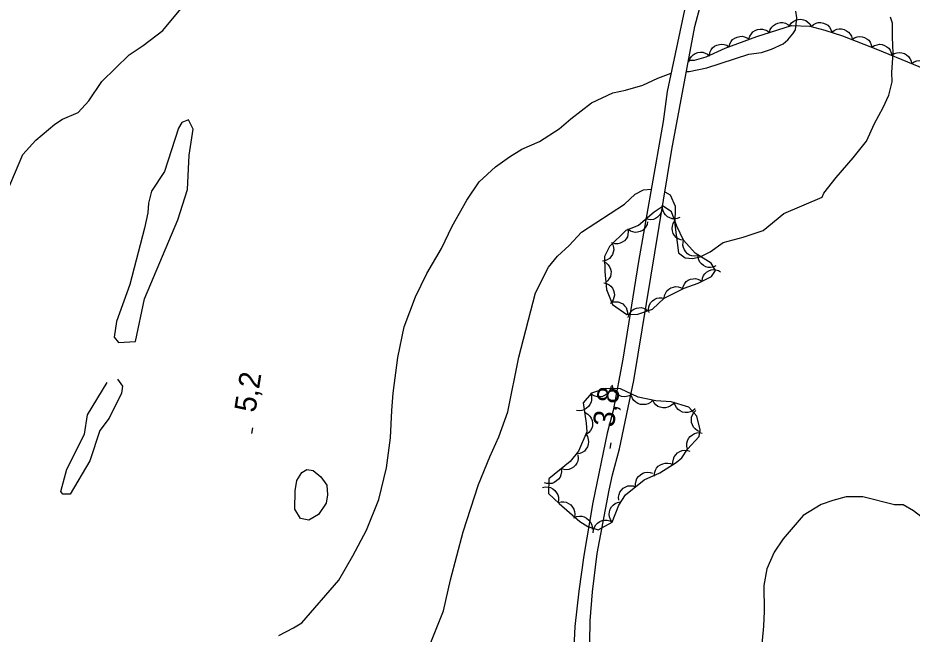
# Model space of a CAD drawing. Extents: x 282461 to 284471, y 5554090 to 5557646.
# Drawn here: x 283624.2 to 283749.2, y 5554829.7 to 5554915.9 of the extents above; entities that cross this region are included whole.
import ezdxf

# ---------------------------------------------------------------- set-up
doc = ezdxf.new("R2010")
doc.units = 0
for name, color, linetype in [('Niveau 1', 7, 'Continuous'), ('Niveau 19', 7, 'Continuous'), ('Niveau 2', 7, 'Continuous'), ('Niveau 3', 7, 'Continuous'), ('Niveau 44', 7, 'Continuous')]:
    doc.layers.add(name, color=color, linetype=linetype)

msp = doc.modelspace()

# ---------------------------------------------------------------- linework, layer by layer
at = {"layer": 'Niveau 1'}
for points in [[(283634.13, 5554904.29), (283635.96, 5554906.98), (283639.76, 5554910.72), (283641.72, 5554912.02), (283644.49, 5554914.13), (283647.01, 5554917.17)], [(283717.72, 5554908.41), (283718.09, 5554908.41), (283720.53, 5554908.89), (283726.44, 5554910.8), (283728.19, 5554911.05), (283729.58, 5554911.53), (283731.2, 5554912.24), (283731.89, 5554912.82), (283732.58, 5554913.64), (283732.92, 5554914.22), (283733.11, 5554915.88), (283732.98, 5554916.81)], [(283660.69, 5554829.5), (283662.78, 5554830.56), (283663.93, 5554831.27), (283669.1, 5554837.23), (283671.04, 5554840.61), (283672.97, 5554844.22), (283674.67, 5554848.52), (283675.78, 5554852.94), (283676.32, 5554857.12), (283676.5, 5554860.95), (283676.71, 5554863.38), (283677.35, 5554868.38), (283678.23, 5554872.68), (283679.81, 5554876.87), (283681.4, 5554880.13), (283683.46, 5554883.62), (283684.94, 5554886.77), (283686.99, 5554890.38), (283688.71, 5554892.95), (283691.01, 5554895.06), (283692.97, 5554896.47), (283694.7, 5554897.53), (283697.14, 5554898.59), (283699.91, 5554900.36), (283701.52, 5554901.76), (283704.41, 5554903.99), (283707.41, 5554905.41), (283709.16, 5554905.77), (283711.59, 5554906.49), (283713.68, 5554907.44), (283715.18, 5554908.03), (283715.58, 5554908.16)], [(283622.09, 5554890.04), (283624.92, 5554896.79), (283626.75, 5554898.78), (283629.4, 5554901.01), (283630.44, 5554901.71), (283632.64, 5554902.66), (283634.13, 5554904.29)]]:
    msp.add_lwpolyline(points, dxfattribs=at)
at = {"layer": 'Niveau 19'}
for points in [[(283720.93, 5554937.34), (283721.46, 5554934.2), (283721.54, 5554932.22), (283721.37, 5554930.64), (283720.93, 5554929.07), (283720.02, 5554926.98), (283718.22, 5554920.81), (283715, 5554905.6), (283714.45, 5554901.38), (283710.98, 5554881.79), (283708.81, 5554868.14), (283707.44, 5554860.94), (283706.6, 5554857.8), (283704.61, 5554848.09), (283703.35, 5554840.67), (283702.64, 5554835.69), (283702.1, 5554830.72), (283701.78, 5554823.99)], [(283704.14, 5554825.54), (283704.24, 5554831.54), (283704.55, 5554835.59), (283705.2, 5554840.97), (283706.91, 5554849.81), (283707.37, 5554851.95), (283708.32, 5554855.61), (283710.35, 5554865.18), (283715.65, 5554897.49), (283718.86, 5554914.7), (283720.66, 5554921.34), (283721.67, 5554924.32), (283724.17, 5554930.5), (283725.38, 5554932.03), (283727.06, 5554933.21), (283728.34, 5554933.96)]]:
    msp.add_lwpolyline(points, dxfattribs=at)
at = {"layer": 'Niveau 2'}
for points in [[(283728.41, 5554886.15), (283731.3, 5554888.5), (283736.67, 5554890.82), (283736.91, 5554891.35), (283738.62, 5554893.58), (283741.02, 5554896.3), (283742.85, 5554898.65), (283743.97, 5554901.11), (283745.22, 5554903.34), (283746.01, 5554905.09), (283746.45, 5554906.96), (283746.43, 5554908.24), (283746.59, 5554910.93), (283746.49, 5554913.2), (283746.5, 5554915.13), (283746.21, 5554915.99)], [(283640.69, 5554870.6), (283641.95, 5554876.56), (283646.57, 5554887.65), (283647.93, 5554891.9), (283648.15, 5554896.66), (283648.71, 5554900.32), (283648.08, 5554901.63), (283647.14, 5554901.27), (283646.69, 5554900.47), (283644.71, 5554894.42), (283642.9, 5554891.64), (283642.48, 5554889.99), (283642.4, 5554888.63), (283641.95, 5554886.48), (283639.87, 5554878.6), (283638.03, 5554873.41), (283637.7, 5554871.23), (283638.27, 5554870.48), (283640.69, 5554870.6)], [(283681.68, 5554827.82), (283683.71, 5554832.95), (283684.71, 5554837.25), (283686.5, 5554844), (283688.64, 5554850.63), (283690.22, 5554854.48), (283691.47, 5554857.27), (283692.71, 5554860.77), (283694.25, 5554868.44), (283696.6, 5554877.4), (283698.42, 5554881.01), (283699.68, 5554882.53), (283701.3, 5554884.06), (283703.02, 5554885.93), (283709.03, 5554889.81), (283710.53, 5554891.22), (283711.69, 5554891.81), (283712.77, 5554891.92)], [(283714.65, 5554891.56), (283715.43, 5554891.15), (283716.14, 5554889.53), (283716.06, 5554886.97), (283716.57, 5554883.03), (283717.51, 5554882.34), (283718.56, 5554882.23), (283719.6, 5554882.48), (283720.99, 5554883.18), (283722.84, 5554884.48), (283725.63, 5554885.2), (283728.41, 5554886.15)], [(283638.15, 5554865.34), (283638.84, 5554864.36), (283638.71, 5554863.38), (283636.99, 5554859.89), (283635.67, 5554858.17), (283634.3, 5554853.93), (283631.53, 5554849.25), (283630.5, 5554849.24), (283630.25, 5554849.61), (283631.05, 5554852.73), (283633.55, 5554857.65), (283633.96, 5554860.34), (283636.71, 5554864.89)], [(283664.9, 5554845.62), (283663.74, 5554845.83), (283662.94, 5554847.14), (283662.99, 5554849.7), (283663.21, 5554851.19), (283663.92, 5554852.28), (283664.63, 5554852.7), (283665.49, 5554852.55), (283666.58, 5554851.7), (283667.4, 5554850.53), (283667.53, 5554849.15), (283667.34, 5554847.98), (283666.24, 5554846.43), (283664.9, 5554845.62)], [(283753.58, 5554826.91), (283755.25, 5554831.82), (283756.15, 5554833.92), (283755.96, 5554838.68), (283755.58, 5554840.88), (283754.39, 5554842.72), (283751.91, 5554845), (283749.44, 5554846.94), (283747.99, 5554847.78), (283746.79, 5554847.77), (283742.35, 5554848.89), (283740.02, 5554848.87), (283738.16, 5554848.39), (283736.54, 5554847.8), (283733.99, 5554846.26), (283731.23, 5554842.99), (283729.97, 5554841.12), (283728.95, 5554838.79), (283728.51, 5554836.47), (283728.55, 5554832.87), (283728.46, 5554830.78), (283728.04, 5554826.25)]]:
    msp.add_lwpolyline(points, dxfattribs=at)
at = {"layer": 'Niveau 3'}
for p, q in [((283656.94, 5554857.74), (283657.06, 5554858.53)), ((283707.05, 5554855.65), (283707.17, 5554856.44))]:
    msp.add_line(p, q, dxfattribs=at)
at = {"layer": 'Niveau 44'}
for points in [[(283729.29, 5554913.85), (283729.41, 5554914.25), (283729.63, 5554914.59), (283729.85, 5554914.84), (283730.14, 5554915.03), (283730.48, 5554915.17), (283730.86, 5554915.23), (283731.19, 5554915.24), (283731.53, 5554915.14), (283731.86, 5554914.98), (283732.15, 5554914.76)], [(283732.13, 5554914.85), (283732.38, 5554915.19), (283732.7, 5554915.43), (283732.99, 5554915.59), (283733.33, 5554915.67), (283733.7, 5554915.69), (283734.08, 5554915.61), (283734.39, 5554915.51), (283734.68, 5554915.31), (283734.94, 5554915.05), (283735.13, 5554914.74)], [(283735.12, 5554914.7), (283735.44, 5554914.98), (283735.81, 5554915.14), (283736.13, 5554915.24), (283736.48, 5554915.24), (283736.84, 5554915.17), (283737.19, 5554915.01), (283737.47, 5554914.85), (283737.7, 5554914.58), (283737.9, 5554914.27), (283738.02, 5554913.93)], [(283718.01, 5554909.97), (283718.82, 5554909.97), (283720.45, 5554910.44), (283723.11, 5554911.63), (283727.52, 5554913.29), (283732.39, 5554914.84), (283734.95, 5554914.75), (283737.05, 5554914.19), (283739.51, 5554913.4), (283744.42, 5554911.47), (283754.36, 5554907.38)], [(283726.43, 5554912.94), (283726.55, 5554913.34), (283726.77, 5554913.68), (283726.99, 5554913.93), (283727.29, 5554914.12), (283727.63, 5554914.26), (283728.01, 5554914.32), (283728.33, 5554914.33), (283728.67, 5554914.23), (283729.01, 5554914.08), (283729.29, 5554913.85)], [(283738.01, 5554913.88), (283738.33, 5554914.14), (283738.71, 5554914.29), (283739.03, 5554914.37), (283739.38, 5554914.35), (283739.74, 5554914.26), (283740.08, 5554914.09), (283740.36, 5554913.91), (283740.58, 5554913.63), (283740.76, 5554913.31), (283740.86, 5554912.97)], [(283723.65, 5554911.83), (283723.74, 5554912.24), (283723.95, 5554912.59), (283724.15, 5554912.85), (283724.44, 5554913.05), (283724.77, 5554913.21), (283725.15, 5554913.29), (283725.47, 5554913.31), (283725.82, 5554913.24), (283726.16, 5554913.1), (283726.45, 5554912.89)], [(283740.83, 5554912.88), (283741.17, 5554913.12), (283741.56, 5554913.24), (283741.89, 5554913.3), (283742.24, 5554913.26), (283742.59, 5554913.15), (283742.92, 5554912.95), (283743.18, 5554912.76), (283743.38, 5554912.47), (283743.54, 5554912.14), (283743.62, 5554911.78)], [(283720.9, 5554910.64), (283720.97, 5554911.05), (283721.15, 5554911.41), (283721.34, 5554911.69), (283721.61, 5554911.91), (283721.94, 5554912.09), (283722.31, 5554912.18), (283722.63, 5554912.23), (283722.98, 5554912.17), (283723.33, 5554912.05), (283723.63, 5554911.86)], [(283743.62, 5554911.8), (283743.97, 5554912.03), (283744.36, 5554912.14), (283744.69, 5554912.2), (283745.04, 5554912.15), (283745.39, 5554912.04), (283745.71, 5554911.84), (283745.97, 5554911.64), (283746.17, 5554911.35), (283746.32, 5554911.01), (283746.4, 5554910.66)], [(283718.04, 5554909.75), (283718.17, 5554910.14), (283718.4, 5554910.48), (283718.63, 5554910.72), (283718.93, 5554910.9), (283719.27, 5554911.03), (283719.65, 5554911.08), (283719.98, 5554911.08), (283720.31, 5554910.97), (283720.65, 5554910.81), (283720.92, 5554910.58)], [(283746.4, 5554910.66), (283746.74, 5554910.89), (283747.13, 5554911), (283747.46, 5554911.06), (283747.81, 5554911.01), (283748.16, 5554910.9), (283748.48, 5554910.7), (283748.74, 5554910.5), (283748.94, 5554910.2), (283749.09, 5554909.87), (283749.17, 5554909.52)], [(283749.17, 5554909.52), (283749.52, 5554909.75), (283749.91, 5554909.86), (283750.23, 5554909.92), (283750.58, 5554909.87), (283750.93, 5554909.76), (283751.26, 5554909.56), (283751.51, 5554909.36), (283751.71, 5554909.06), (283751.87, 5554908.73), (283751.94, 5554908.38)], [(283714.58, 5554876.66), (283717.36, 5554878.08), (283719.33, 5554878.79), (283721.18, 5554879.73), (283721.76, 5554880.55), (283721.16, 5554881.59), (283718.93, 5554882.96), (283717.28, 5554884.81), (283716.33, 5554886.77), (283715.61, 5554888.74), (283714.43, 5554889.54), (283713.16, 5554888.72), (283710.97, 5554886.84), (283709.23, 5554886.13), (283706.93, 5554883.9), (283706.25, 5554882.5), (283706.27, 5554880.42), (283706.53, 5554877.87), (283707.37, 5554875.78), (283709.37, 5554874.41), (283710.88, 5554874.42), (283712.97, 5554875.14), (283714.58, 5554876.66)], [(283714.24, 5554889.65), (283714.29, 5554889.24), (283714.22, 5554888.86), (283714.12, 5554888.55), (283713.92, 5554888.27), (283713.67, 5554888.01), (283713.35, 5554887.82), (283713.07, 5554887.69), (283712.73, 5554887.65), (283712.37, 5554887.66), (283712.03, 5554887.75)], [(283716.77, 5554887.96), (283716.39, 5554887.8), (283716, 5554887.77), (283715.68, 5554887.79), (283715.36, 5554887.9), (283715.04, 5554888.07), (283714.77, 5554888.33), (283714.57, 5554888.57), (283714.44, 5554888.89), (283714.36, 5554889.24), (283714.36, 5554889.59)], [(283717.29, 5554884.78), (283716.89, 5554884.84), (283716.54, 5554885), (283716.27, 5554885.18), (283716.04, 5554885.44), (283715.86, 5554885.74), (283715.76, 5554886.1), (283715.7, 5554886.41), (283715.75, 5554886.75), (283715.85, 5554887.1), (283716.02, 5554887.4)], [(283709.49, 5554886.38), (283709.56, 5554885.99), (283709.52, 5554885.59), (283709.44, 5554885.28), (283709.26, 5554884.99), (283709.03, 5554884.72), (283708.72, 5554884.51), (283708.44, 5554884.36), (283708.1, 5554884.3), (283707.74, 5554884.29), (283707.4, 5554884.36)], [(283712.26, 5554887.37), (283712.18, 5554886.97), (283711.99, 5554886.63), (283711.8, 5554886.37), (283711.53, 5554886.16), (283711.21, 5554886), (283710.85, 5554885.92), (283710.53, 5554885.88), (283710.2, 5554885.95), (283709.86, 5554886.07), (283709.57, 5554886.27)], [(283707.22, 5554884.49), (283707.42, 5554884.14), (283707.51, 5554883.76), (283707.54, 5554883.44), (283707.47, 5554883.1), (283707.35, 5554882.77), (283707.13, 5554882.46), (283706.92, 5554882.23), (283706.63, 5554882.05), (283706.29, 5554881.92), (283705.95, 5554881.87)], [(283719.24, 5554882.61), (283718.84, 5554882.56), (283718.45, 5554882.62), (283718.14, 5554882.71), (283717.86, 5554882.9), (283717.6, 5554883.15), (283717.4, 5554883.46), (283717.26, 5554883.75), (283717.21, 5554884.09), (283717.22, 5554884.45), (283717.3, 5554884.78)], [(283721.81, 5554881.19), (283721.44, 5554881.02), (283721.05, 5554880.97), (283720.73, 5554880.97), (283720.4, 5554881.07), (283720.08, 5554881.23), (283719.8, 5554881.48), (283719.58, 5554881.71), (283719.44, 5554882.02), (283719.34, 5554882.37), (283719.33, 5554882.72)], [(283706.13, 5554881.8), (283706.49, 5554881.6), (283706.77, 5554881.32), (283706.96, 5554881.07), (283707.08, 5554880.75), (283707.15, 5554880.4), (283707.12, 5554880.03), (283707.07, 5554879.71), (283706.91, 5554879.41), (283706.69, 5554879.12), (283706.43, 5554878.9)], [(283719.87, 5554879.07), (283719.92, 5554879.47), (283720.08, 5554879.83), (283720.25, 5554880.1), (283720.51, 5554880.33), (283720.81, 5554880.52), (283721.17, 5554880.63), (283721.48, 5554880.69), (283721.82, 5554880.65), (283722.16, 5554880.55), (283722.47, 5554880.38)], [(283706.14, 5554878.83), (283706.54, 5554878.74), (283706.89, 5554878.55), (283707.14, 5554878.36), (283707.35, 5554878.09), (283707.51, 5554877.77), (283707.59, 5554877.4), (283707.62, 5554877.09), (283707.55, 5554876.75), (283707.43, 5554876.42), (283707.23, 5554876.13)], [(283717.16, 5554878.01), (283717.26, 5554878.4), (283717.47, 5554878.74), (283717.67, 5554878.99), (283717.95, 5554879.18), (283718.27, 5554879.33), (283718.64, 5554879.4), (283718.96, 5554879.42), (283719.29, 5554879.34), (283719.62, 5554879.2), (283719.9, 5554879)], [(283714.58, 5554876.66), (283714.63, 5554877.06), (283714.79, 5554877.42), (283714.96, 5554877.7), (283715.21, 5554877.92), (283715.52, 5554878.11), (283715.87, 5554878.23), (283716.18, 5554878.29), (283716.52, 5554878.25), (283716.87, 5554878.15), (283717.17, 5554877.98)], [(283707.06, 5554875.99), (283707.44, 5554876.14), (283707.83, 5554876.17), (283708.15, 5554876.16), (283708.47, 5554876.04), (283708.78, 5554875.87), (283709.05, 5554875.61), (283709.26, 5554875.36), (283709.38, 5554875.05), (283709.46, 5554874.7), (283709.46, 5554874.35)], [(283712.46, 5554874.66), (283712.4, 5554875.06), (283712.45, 5554875.45), (283712.53, 5554875.76), (283712.71, 5554876.05), (283712.95, 5554876.32), (283713.26, 5554876.53), (283713.54, 5554876.67), (283713.88, 5554876.73), (283714.24, 5554876.74), (283714.58, 5554876.66)], [(283709.56, 5554873.96), (283709.66, 5554874.36), (283709.87, 5554874.69), (283710.08, 5554874.94), (283710.36, 5554875.13), (283710.69, 5554875.27), (283711.05, 5554875.33), (283711.37, 5554875.35), (283711.7, 5554875.27), (283712.03, 5554875.12), (283712.31, 5554874.91)], [(283717.85, 5554855.56), (283719.46, 5554857.34), (283719.59, 5554858.25), (283719.16, 5554860.17), (283718.05, 5554861.44), (283715.58, 5554862.16), (283713.43, 5554862.31), (283710.95, 5554862.81), (283708.48, 5554863.98), (283706.33, 5554864.02), (283704.4, 5554863.37), (283703.25, 5554862.04), (283703.66, 5554859.21), (283703.76, 5554857.96), (283702.59, 5554855.27), (283701.44, 5554853.82), (283698.46, 5554851.38), (283698.43, 5554849.35), (283699.88, 5554847.97), (283702.78, 5554845.43), (283703.9, 5554844.73), (283705.37, 5554844.26), (283707.3, 5554845.35), (283708.24, 5554847.71), (283709.17, 5554849.16), (283711.8, 5554851.26), (283713.96, 5554852.24), (283716.24, 5554853.67), (283717.04, 5554854.33), (283717.85, 5554855.56)], [(283707.16, 5554864.3), (283707.05, 5554863.89), (283706.83, 5554863.54), (283706.61, 5554863.29), (283706.32, 5554863.09), (283705.97, 5554862.94), (283705.59, 5554862.88), (283705.26, 5554862.86), (283704.91, 5554862.96), (283704.57, 5554863.11), (283704.28, 5554863.33)], [(283710.08, 5554863.22), (283709.71, 5554863.01), (283709.31, 5554862.91), (283708.98, 5554862.88), (283708.63, 5554862.94), (283708.28, 5554863.07), (283707.96, 5554863.29), (283707.71, 5554863.51), (283707.53, 5554863.82), (283707.39, 5554864.16), (283707.33, 5554864.52)], [(283704.32, 5554863.28), (283704.43, 5554862.87), (283704.42, 5554862.46), (283704.36, 5554862.13), (283704.2, 5554861.81), (283703.98, 5554861.5), (283703.69, 5554861.25), (283703.41, 5554861.07), (283703.07, 5554860.98), (283702.69, 5554860.93), (283702.33, 5554860.98)], [(283712.98, 5554862.4), (283712.68, 5554862.1), (283712.32, 5554861.91), (283712, 5554861.8), (283711.65, 5554861.78), (283711.27, 5554861.82), (283710.91, 5554861.96), (283710.62, 5554862.11), (283710.36, 5554862.36), (283710.14, 5554862.66), (283710, 5554863)], [(283716.01, 5554862.13), (283715.75, 5554861.8), (283715.41, 5554861.56), (283715.11, 5554861.41), (283714.76, 5554861.34), (283714.39, 5554861.33), (283714.01, 5554861.42), (283713.7, 5554861.54), (283713.42, 5554861.75), (283713.16, 5554862.03), (283712.98, 5554862.34)], [(283718.91, 5554861.19), (283718.58, 5554860.92), (283718.2, 5554860.76), (283717.88, 5554860.67), (283717.52, 5554860.68), (283717.16, 5554860.75), (283716.81, 5554860.92), (283716.53, 5554861.1), (283716.3, 5554861.37), (283716.1, 5554861.69), (283715.99, 5554862.04)], [(283703.54, 5554860.66), (283703.91, 5554860.45), (283704.2, 5554860.15), (283704.39, 5554859.88), (283704.51, 5554859.55), (283704.57, 5554859.18), (283704.54, 5554858.79), (283704.48, 5554858.47), (283704.3, 5554858.15), (283704.07, 5554857.86), (283703.79, 5554857.63)], [(283719.65, 5554857.98), (283719.26, 5554858.13), (283718.93, 5554858.39), (283718.7, 5554858.63), (283718.54, 5554858.94), (283718.42, 5554859.3), (283718.4, 5554859.69), (283718.42, 5554860.02), (283718.55, 5554860.35), (283718.74, 5554860.68), (283718.99, 5554860.94)], [(283703.63, 5554857.66), (283703.85, 5554857.3), (283703.96, 5554856.9), (283704.01, 5554856.57), (283703.96, 5554856.22), (283703.84, 5554855.86), (283703.63, 5554855.54), (283703.42, 5554855.28), (283703.12, 5554855.09), (283702.77, 5554854.94), (283702.42, 5554854.87)], [(283717.85, 5554855.56), (283717.75, 5554855.97), (283717.77, 5554856.38), (283717.83, 5554856.71), (283718, 5554857.03), (283718.22, 5554857.33), (283718.53, 5554857.57), (283718.81, 5554857.74), (283719.15, 5554857.83), (283719.53, 5554857.86), (283719.89, 5554857.81)], [(283715.83, 5554853.33), (283715.79, 5554853.75), (283715.87, 5554854.16), (283715.98, 5554854.47), (283716.19, 5554854.76), (283716.46, 5554855.03), (283716.79, 5554855.22), (283717.1, 5554855.35), (283717.45, 5554855.39), (283717.83, 5554855.37), (283718.18, 5554855.27)], [(283702.53, 5554854.72), (283702.57, 5554854.29), (283702.49, 5554853.89), (283702.38, 5554853.57), (283702.17, 5554853.29), (283701.9, 5554853.02), (283701.56, 5554852.83), (283701.26, 5554852.7), (283700.91, 5554852.66), (283700.53, 5554852.69), (283700.18, 5554852.79)], [(283700.18, 5554852.79), (283700.22, 5554852.37), (283700.14, 5554851.96), (283700.03, 5554851.65), (283699.82, 5554851.36), (283699.55, 5554851.1), (283699.21, 5554850.91), (283698.91, 5554850.77), (283698.55, 5554850.74), (283698.18, 5554850.76), (283697.83, 5554850.86)], [(283713.22, 5554851.77), (283713.23, 5554852.2), (283713.36, 5554852.59), (283713.51, 5554852.89), (283713.76, 5554853.15), (283714.06, 5554853.37), (283714.41, 5554853.52), (283714.73, 5554853.61), (283715.09, 5554853.61), (283715.46, 5554853.54), (283715.79, 5554853.39)], [(283710.59, 5554850.3), (283710.56, 5554850.72), (283710.65, 5554851.12), (283710.76, 5554851.43), (283710.97, 5554851.72), (283711.25, 5554851.98), (283711.59, 5554852.17), (283711.89, 5554852.3), (283712.24, 5554852.33), (283712.62, 5554852.3), (283712.97, 5554852.19)], [(283697.55, 5554850.19), (283697.96, 5554850.28), (283698.37, 5554850.25), (283698.7, 5554850.18), (283699.01, 5554850), (283699.31, 5554849.77), (283699.54, 5554849.46), (283699.71, 5554849.18), (283699.79, 5554848.83), (283699.81, 5554848.45), (283699.75, 5554848.09)], [(283708.22, 5554848.4), (283708.18, 5554848.82), (283708.27, 5554849.22), (283708.39, 5554849.54), (283708.6, 5554849.82), (283708.87, 5554850.08), (283709.21, 5554850.27), (283709.51, 5554850.4), (283709.87, 5554850.43), (283710.24, 5554850.4), (283710.59, 5554850.3)], [(283699.75, 5554848.09), (283700.16, 5554848.19), (283700.57, 5554848.18), (283700.9, 5554848.12), (283701.22, 5554847.96), (283701.52, 5554847.74), (283701.76, 5554847.44), (283701.94, 5554847.16), (283702.04, 5554846.82), (283702.08, 5554846.45), (283702.03, 5554846.08)], [(283707.3, 5554845.35), (283707.06, 5554845.7), (283706.94, 5554846.1), (283706.89, 5554846.43), (283706.93, 5554846.78), (283707.04, 5554847.14), (283707.24, 5554847.47), (283707.44, 5554847.73), (283707.73, 5554847.94), (283708.07, 5554848.1), (283708.43, 5554848.18)], [(283701.94, 5554845.96), (283702.32, 5554846.13), (283702.73, 5554846.18), (283703.07, 5554846.17), (283703.41, 5554846.07), (283703.74, 5554845.9), (283704.03, 5554845.64), (283704.25, 5554845.4), (283704.4, 5554845.07), (283704.5, 5554844.71), (283704.51, 5554844.35)], [(283704.66, 5554843.86), (283704.69, 5554844.28), (283704.84, 5554844.66), (283705.01, 5554844.95), (283705.26, 5554845.2), (283705.57, 5554845.42), (283705.93, 5554845.55), (283706.26, 5554845.63), (283706.61, 5554845.6), (283706.98, 5554845.51), (283707.3, 5554845.35)]]:
    msp.add_lwpolyline(points, dxfattribs=at)

# ---------------------------------------------------------------- texts
at = {"layer": 'Niveau 3'}
for s, p in [('5,2  ', (283657.42, 5554860.58)), ('3,8  ', (283707.53, 5554858.49))]:
    msp.add_text(s, height=3, rotation=81.0957, dxfattribs=at).set_placement(p)

doc.saveas('drawing.dxf')
